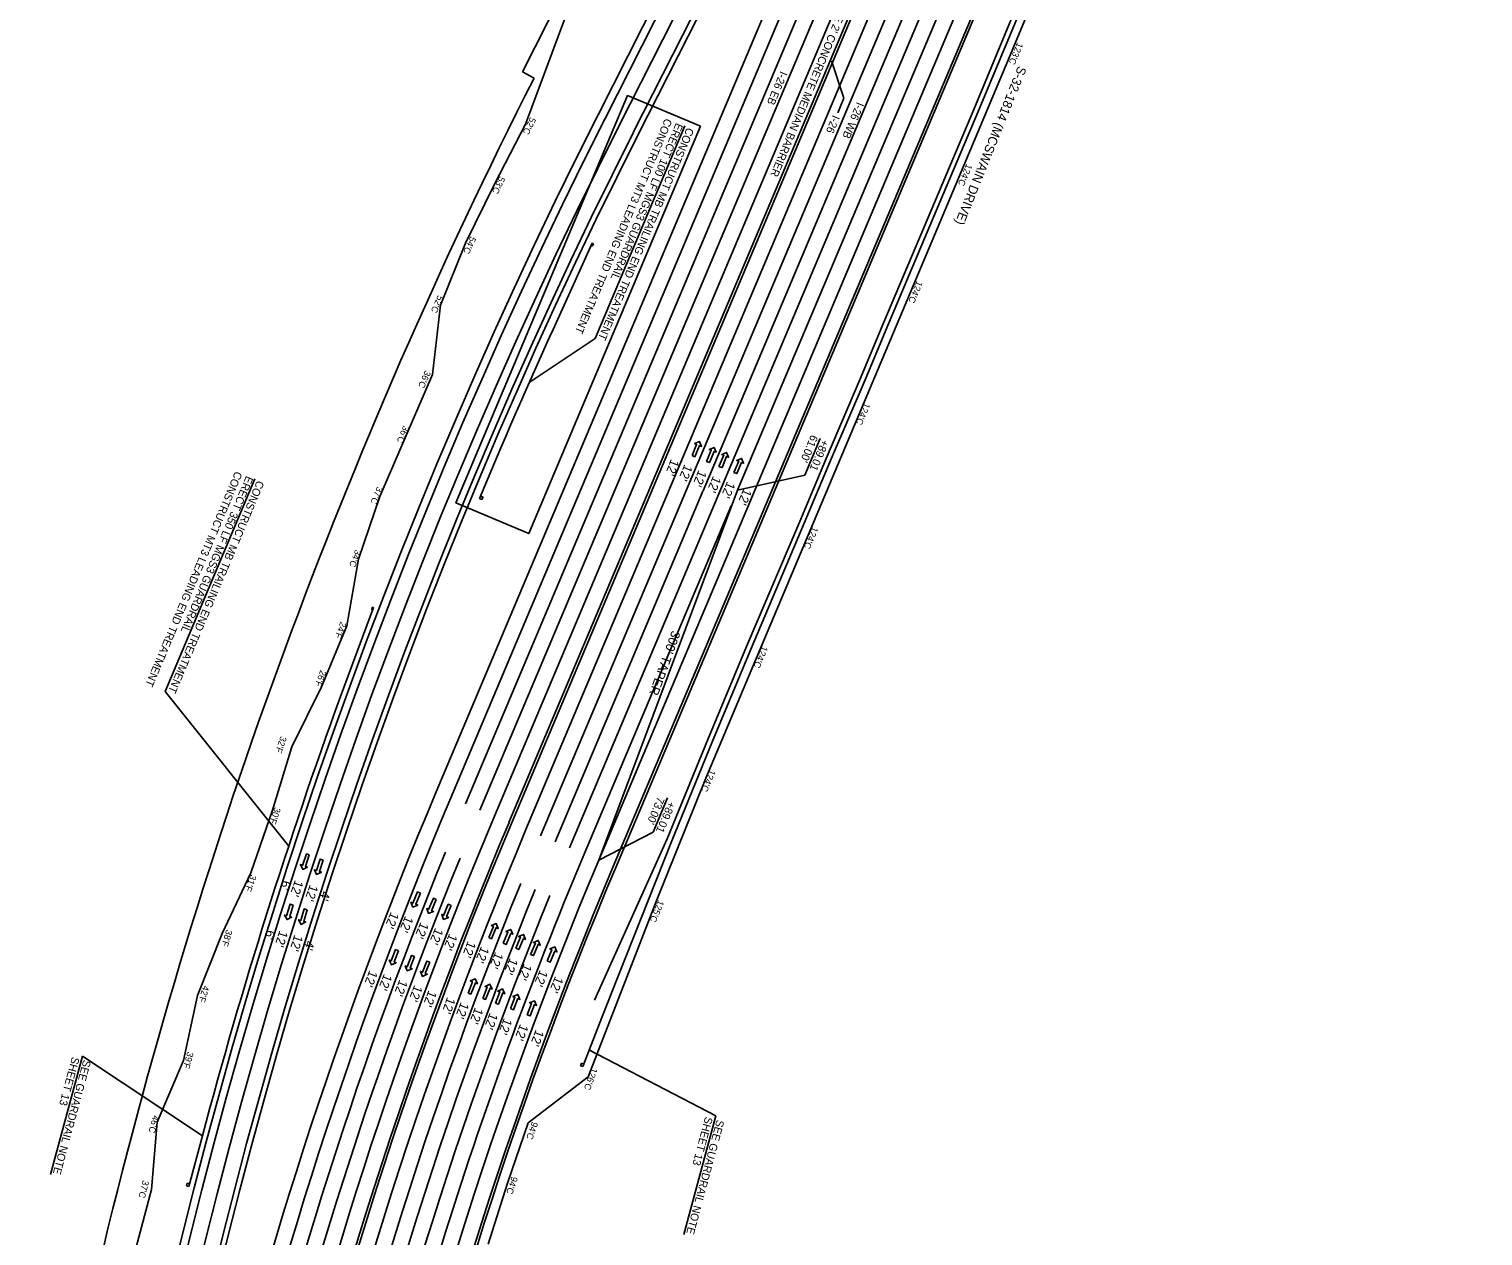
# Model space of a CAD drawing. Extents: x 1966090 to 1975830, y 788086 to 801233.
# Drawn here: x 1966292 to 1967397, y 791849 to 792766 of the extents above; entities that cross this region are included whole.
import ezdxf

# ---------------------------------------------------------------- set-up
doc = ezdxf.new("R2010")
doc.units = 0
for name, color, linetype in [('BR_PRESTRESSED BEAM', 7, 'Continuous'), ('BR_PROPOSED_DRAINAGE', 7, 'Continuous'), ('BR_REBAR', 7, 'Continuous'), ('RD_EX_Driveway_txCode', 7, 'Continuous'), ('RD_EX_RW_TX', 7, 'Continuous'), ('RD_EX_SU_Gas', 7, 'Continuous'), ('RD_EX_SU_H2O', 7, 'Continuous'), ('RD_EX_TX_Dam_ELEV', 7, 'Continuous'), ('RD_PD_PaveShd', 7, 'Continuous'), ('RD_Sketch6', 7, 'Continuous'), ('RD_Sketch8', 7, 'Continuous')]:
    doc.layers.add(name, color=color, linetype=linetype)

msp = doc.modelspace()

# ---------------------------------------------------------------- linework, layer by layer
at = {"layer": 'BR_PRESTRESSED BEAM'}
for p, q in [((1966690.3, 792537.7), (1966720.1, 792603.3)), ((1966719.3, 792601.4), (1966720.1, 792603.3)), ((1966720, 792601.1), (1966719.3, 792601.4)), ((1966721, 792602.9), (1966720, 792601.1)), ((1966720.1, 792603.3), (1966721, 792602.9)), ((1966649.9, 792446.2), (1966634.4, 792409.4)), ((1966635.2, 792411.2), (1966634.4, 792409.4)), ((1966634.4, 792409.4), (1966636.3, 792408.6)), ((1966637.1, 792410.4), (1966635.2, 792411.2)), ((1966636.3, 792408.6), (1966637.1, 792410.4)), ((1966528.8, 792258.9), (1966554, 792326.4)), ((1966553, 792326.7), (1966552.6, 792324.8)), ((1966552.6, 792324.8), (1966553.3, 792324.5)), ((1966554, 792326.4), (1966553, 792326.7)), ((1966553.3, 792324.5), (1966554, 792326.4)), ((1966727.5, 792014.9), (1966713, 791977.6)), ((1966711.2, 791978.3), (1966711.9, 791980.2)), ((1966713, 791977.6), (1966711.2, 791978.3)), ((1966711.9, 791980.2), (1966713.8, 791979.5)), ((1966713.8, 791979.5), (1966713, 791977.6)), ((1966423.9, 791925.1), (1966413.7, 791886.4)), ((1966411.8, 791886.9), (1966412.3, 791888.9)), ((1966413.7, 791886.4), (1966411.8, 791886.9)), ((1966412.3, 791888.9), (1966414.2, 791888.4)), ((1966414.2, 791888.4), (1966413.7, 791886.4))]:
    msp.add_line(p, q, dxfattribs=at)
msp.add_lwpolyline([(1966727.5, 792014.9), (1966739.3, 792045), (1966780.5, 792149.2), (1966780.6, 792149.3), (1966811.4, 792224.9), (1966840.8, 792295.4), (1966881.1, 792390.5), (1966902, 792440), (1966926.6, 792497.7), (1966945.1, 792542), (1966981.4, 792627.9), (1967013.4, 792703.6), (1967044.7, 792778.8), (1967071.9, 792844.4), (1967099.3, 792909.5), (1967127.2, 792975.7), (1967171.8, 793081), (1967207.1, 793164.5), (1967218.3, 793191.6)], dxfattribs=at)
for radius, start, end in [(3966, 155.4648, 156.9094), (4010, 160.0521, 165.053)]:
    msp.add_arc((1970298.2, 790890.8), radius, start, end, dxfattribs=at)
at = {"layer": 'BR_PROPOSED_DRAINAGE'}
for p, q in [((1967077.5, 792842.1), (1967039.1, 792749.8)), ((1966704.5, 792788.6), (1966669.5, 792693.8)), ((1967039.1, 792749.8), (1967000.5, 792657.6)), ((1966669.5, 792693.8), (1966646.2, 792648.8)), ((1966646.2, 792648.8), (1966623.8, 792603.3)), ((1967000.5, 792657.6), (1966806.4, 792196.7)), ((1966623.8, 792603.3), (1966604.8, 792556.3)), ((1966604.8, 792556.3), (1966598.6, 792503.7)), ((1966598.6, 792503.7), (1966578.8, 792457.3)), ((1966578.8, 792457.3), (1966558.8, 792411)), ((1966558.8, 792411), (1966542.5, 792363.2)), ((1966542.5, 792363.2), (1966533.7, 792312.7)), ((1966514.4, 792266.1), (1966533.7, 792312.7)), ((1966514.4, 792266.1), (1966491.8, 792220.7)), ((1966491.8, 792220.7), (1966477.2, 792172.5)), ((1966806.4, 792196.7), (1966769.2, 792104.4)), ((1966477.2, 792172.5), (1966460.6, 792124.9)), ((1966460.6, 792124.9), (1966438.9, 792078.8)), ((1966769.2, 792104.4), (1966717, 791969.9)), ((1966438.9, 792078.8), (1966420.2, 792031.7)), ((1966420.2, 792031.7), (1966409.6, 791982.2)), ((1966389.5, 791935.3), (1966409.6, 791982.2)), ((1966717, 791969.9), (1966671.4, 791934.9)), ((1966389.5, 791935.3), (1966385.1, 791884.3)), ((1966671.4, 791934.9), (1966655.8, 791888.9)), ((1966655.8, 791888.9), (1966640.9, 791842.7)), ((1966385.1, 791884.3), (1966372.2, 791835.5))]:
    msp.add_line(p, q, dxfattribs=at)
at = {"layer": 'BR_REBAR'}
for p, q in [((1967372.9, 793640.1), (1966736.1, 792129.8)), ((1967374.7, 793639.3), (1966737.9, 792129))]:
    msp.add_line(p, q, dxfattribs=at)
for radius, end in [(3190, 179.2174), (3188, 179.2164)]:
    msp.add_arc((1969675.5, 790890.4), radius, 157.1374, end, dxfattribs=at)
at = {"layer": 'RD_EX_Driveway_txCode'}
for points in [[(1966795.9, 792442.1), (1966798.1, 792441.1), (1966801.7, 792449.6), (1966803.2, 792448.9), (1966801.7, 792452.6), (1966797.9, 792451.1), (1966799.4, 792450.5)], [(1966806.9, 792437.6), (1966809.1, 792436.7), (1966812.7, 792445.1), (1966814.2, 792444.5), (1966812.7, 792448.2), (1966809, 792446.7), (1966810.5, 792446.1)], [(1966816.4, 792433.8), (1966818.7, 792432.9), (1966822.2, 792441.3), (1966823.7, 792440.7), (1966822.2, 792444.4), (1966818.5, 792442.9), (1966820, 792442.2)], [(1966827.8, 792429.2), (1966830, 792428.3), (1966833.6, 792436.7), (1966835.1, 792436.1), (1966833.6, 792439.8), (1966829.9, 792438.3), (1966831.4, 792437.7)], [(1966505.1, 792138.5), (1966502.9, 792139.2), (1966499.9, 792130.5), (1966498.4, 792131.1), (1966500.2, 792127.5), (1966503.7, 792129.2), (1966502.2, 792129.8)], [(1966515.7, 792134.6), (1966513.4, 792135.3), (1966510.5, 792126.7), (1966509, 792127.2), (1966510.7, 792123.6), (1966514.3, 792125.4), (1966512.8, 792125.9)], [(1966589.6, 792109.4), (1966587.4, 792110.3), (1966583.8, 792101.9), (1966582.3, 792102.5), (1966583.8, 792098.8), (1966587.5, 792100.3), (1966586, 792101)], [(1966492.9, 792100.4), (1966490.6, 792101.1), (1966487.9, 792092.3), (1966486.3, 792092.8), (1966488.2, 792089.3), (1966491.7, 792091.1), (1966490.2, 792091.6)], [(1966503.6, 792096.7), (1966501.3, 792097.5), (1966498.6, 792088.7), (1966497, 792089.2), (1966498.9, 792085.6), (1966502.4, 792087.5), (1966500.9, 792088)], [(1966601.6, 792104.6), (1966599.4, 792105.5), (1966595.8, 792097.1), (1966594.3, 792097.7), (1966595.8, 792094), (1966599.5, 792095.5), (1966598, 792096.1)], [(1966613, 792100), (1966610.7, 792101), (1966607.2, 792092.5), (1966605.7, 792093.2), (1966607.2, 792089.4), (1966610.9, 792090.9), (1966609.4, 792091.6)], [(1966641.4, 792075.7), (1966643.6, 792074.8), (1966647.2, 792083.2), (1966648.7, 792082.6), (1966647.2, 792086.3), (1966643.5, 792084.8), (1966645, 792084.2)], [(1966652.5, 792071.3), (1966654.7, 792070.4), (1966658.2, 792078.8), (1966659.7, 792078.2), (1966658.2, 792081.9), (1966654.5, 792080.4), (1966656, 792079.7)], [(1966662, 792067.5), (1966664.2, 792066.5), (1966667.8, 792075), (1966669.3, 792074.3), (1966667.8, 792078.1), (1966664.1, 792076.6), (1966665.6, 792075.9)], [(1966573, 792065.6), (1966570.7, 792066.5), (1966567.4, 792058), (1966565.9, 792058.6), (1966567.5, 792054.9), (1966571.1, 792056.5), (1966569.6, 792057.1)], [(1966673.3, 792062.9), (1966675.5, 792062), (1966679.1, 792070.4), (1966680.6, 792069.8), (1966679.1, 792073.5), (1966675.4, 792072), (1966676.9, 792071.4)], [(1966685.9, 792057.9), (1966688.1, 792056.9), (1966691.7, 792065.4), (1966693.2, 792064.8), (1966691.7, 792068.5), (1966688, 792067), (1966689.5, 792066.3)], [(1966585.1, 792061.2), (1966582.8, 792062.1), (1966579.5, 792053.5), (1966578, 792054.1), (1966579.6, 792050.4), (1966583.2, 792052), (1966581.7, 792052.6)], [(1966596.6, 792057), (1966594.3, 792057.8), (1966591, 792049.3), (1966589.5, 792049.9), (1966591.1, 792046.2), (1966594.7, 792047.8), (1966593.2, 792048.4)], [(1966625.7, 792033.5), (1966627.9, 792032.7), (1966631.3, 792041.2), (1966632.8, 792040.6), (1966631.2, 792044.3), (1966627.5, 792042.7), (1966629, 792042.1)], [(1966636.9, 792029.4), (1966639.1, 792028.6), (1966642.5, 792037.1), (1966644, 792036.5), (1966642.4, 792040.2), (1966638.7, 792038.6), (1966640.2, 792038)], [(1966646.5, 792025.9), (1966648.8, 792025), (1966652.1, 792033.6), (1966653.6, 792033), (1966652, 792036.6), (1966648.3, 792035), (1966649.9, 792034.4)], [(1966658, 792021.7), (1966660.2, 792020.8), (1966663.6, 792029.3), (1966665.1, 792028.7), (1966663.5, 792032.4), (1966659.8, 792030.8), (1966661.3, 792030.2)], [(1966670.7, 792017), (1966672.9, 792016.1), (1966676.3, 792024.7), (1966677.8, 792024.1), (1966676.2, 792027.7), (1966672.5, 792026.1), (1966674, 792025.5)]]:
    msp.add_lwpolyline(points, close=True, dxfattribs=at)
at = {"layer": 'RD_EX_SU_Gas'}
for p, q in [((1967295.5, 793770.5), (1966623.7, 792177.2)), ((1967306.5, 793765.8), (1966634.7, 792172.5)), ((1967352.6, 793746.4), (1966680.8, 792153.1)), ((1967374.7, 793737.1), (1966702.9, 792143.8)), ((1967363.7, 793741.7), (1966804.4, 792415.3)), ((1966740.5, 792692.8), (1966970.9, 793147.7)), ((1966804.2, 792414.9), (1966691.9, 792148.4)), ((1966714, 792139.1), (1966825.6, 792403.9))]:
    msp.add_line(p, q, dxfattribs=at)
for centre, radius, start, end in [((1970298.2, 790890.8), 3988, 153.1374, 186.3991), ((1969675.5, 790890.4), 3312, 157.822, 177.0114), ((1969675.5, 790890.4), 3300, 157.822, 177.0114), ((1969675.5, 790890.4), 3214, 157.1374, 162.7868), ((1969675.5, 790890.4), 3250, 157.8325, 179.1982), ((1969675.5, 790890.4), 3238, 157.8325, 179.1982), ((1969675.5, 790890.4), 3226, 157.8325, 179.1982)]:
    msp.add_arc(centre, radius, start, end, dxfattribs=at)
at = {"layer": 'RD_EX_TX_Dam_ELEV'}
for p, q in [((1966919.3, 793231.7), (1966667, 792733.5)), ((1966667, 792733.5), (1966675.9, 792728.9)), ((1966721.7, 792028.1), (1966777.1, 792150.7))]:
    msp.add_line(p, q, dxfattribs=at)
msp.add_lwpolyline([(1966777.1, 792150.7), (1966808, 792226.3), (1966837.4, 792296.9), (1966877.7, 792392), (1966898.6, 792441.5), (1966923.1, 792499.1), (1966941.6, 792543.4), (1966978, 792629.4), (1967010, 792705), (1967041.2, 792780.2), (1967068.5, 792845.9), (1967095.9, 792910.9), (1967123.7, 792977.2), (1967168.4, 793082.5), (1967203.6, 793165.9), (1967286.6, 793366.3)], dxfattribs=at)
msp.add_arc((1970298.2, 790890.8), 4062, 153.0951, 166.4711, dxfattribs=at)
at = {"layer": 'RD_PD_PaveShd'}
for p, q in [((1967328.6, 793756.5), (1966656.8, 792163.2)), ((1967330.5, 793755.7), (1966658.7, 792162.4)), ((1967372.9, 793640.1), (1966736.1, 792129.8)), ((1966724.5, 792701), (1966976.8, 793199.2)), ((1966754.8, 792685.6), (1966991.1, 793152.1)), ((1966933.9, 792974.6), (1966601.6, 792186.5))]:
    msp.add_line(p, q, dxfattribs=at)
for centre, radius, start, end in [((1970298.2, 790890.8), 4006, 153.1374, 186.3991), ((1970298.2, 790890.8), 3972, 153.1374, 186.1282), ((1969675.5, 790890.4), 3336, 157.1374, 177.0114), ((1969675.5, 790890.4), 3276, 157.1374, 179.1982), ((1969675.5, 790890.4), 3274, 157.1374, 179.1982), ((1969675.5, 790890.4), 3190, 157.1374, 179.2174)]:
    msp.add_arc(centre, radius, start, end, dxfattribs=at)
at = {"layer": 'RD_Sketch6'}
for p, q in [((1966911.3, 792713.5), (1966902, 792742.1)), ((1966906.7, 792702.5), (1966911.3, 792713.5)), ((1966790.4, 792692.5), (1966722.2, 792530.9)), ((1966722.2, 792530.9), (1966672.9, 792497.9)), ((1966881.6, 792427.2), (1966893.2, 792454.9)), ((1966463.8, 792424.3), (1966395.6, 792262.7)), ((1966395.6, 792262.7), (1966489.5, 792145.2)), ((1966766.3, 792155.8), (1966777.3, 792181.8)), ((1966717.6, 791990.3), (1966813.9, 791940.1)), ((1966308.5, 791895.5), (1966332.8, 791985.6)), ((1966423.9, 791925.1), (1966332.8, 791985.6)), ((1966789.7, 791850), (1966813.9, 791940.1))]:
    msp.add_line(p, q, dxfattribs=at)
msp.add_lwpolyline([(1966802.4, 792692.3), (1966671.8, 792382.7), (1966616.5, 792406.1), (1966747, 792715.6)], close=True, dxfattribs=at)
for points in [[(1966881.6, 792427.2), (1966830.5, 792415.6)], [(1966766.3, 792155.8), (1966725, 792134.5)]]:
    msp.add_lwpolyline(points, dxfattribs=at)
at = {"layer": 'RD_Sketch8'}
for p, q in [((1967317.6, 793761.2), (1966645.8, 792167.9)), ((1967341.5, 793751.1), (1966669.7, 792157.8)), ((1967385.8, 793732.4), (1966830.5, 792415.6)), ((1967396.8, 793727.8), (1966725, 792134.5)), ((1966729.8, 792698.2), (1966982.2, 793196.5)), ((1966751.2, 792687.4), (1967003.6, 793185.6)), ((1966933.3, 792942.5), (1966612.6, 792181.9)), ((1966830.5, 792415.6), (1966725, 792134.5))]:
    msp.add_line(p, q, dxfattribs=at)
for centre, radius, start, end in [((1970298.2, 790890.8), 4000, 153.1374, 186.3991), ((1970298.2, 790890.8), 3976, 153.1374, 186.1303), ((1969675.5, 790890.4), 3324, 157.1374, 177.0114), ((1969675.5, 790890.4), 3288, 157.1374, 177.0114), ((1969675.5, 790890.4), 3262, 157.1374, 179.1982), ((1969675.5, 790890.4), 3202, 157.1374, 179.1982)]:
    msp.add_arc(centre, radius, start, end, dxfattribs=at)

# ---------------------------------------------------------------- texts
at = {"layer": 'RD_EX_Driveway_txCode'}
for s, height, rotation, p in [("REMOVE AND REPLACE 2' CONCRETE MEDIAN BARRIER", 6, 247.4535, (1966939.8, 792858.9)), ("12'", 7, 248.9372, (1966780, 792439.7)), ("12'", 7, 246.981, (1966790.3, 792435.7)), ("12'", 7, 246.981, (1966801, 792431.4)), ("12'", 7, 246.981, (1966812, 792426.9)), ("12'", 7, 246.981, (1966822.7, 792422.7)), ("12'", 7, 246.981, (1966835.2, 792417.4)), ("300' TAPER", 7, 250.0706, (1966780.7, 792309.4)), ("6'", 7, 257.2178, (1966484.4, 792119.5)), ("12'", 7, 250.689, (1966494.3, 792119.8)), ("12'", 7, 250.689, (1966505.6, 792116.3)), ("4'", 7, 255.0854, (1966514.4, 792111.4)), ("12'", 7, 246.981, (1966567.2, 792095.6)), ("12'", 7, 246.981, (1966578.1, 792092.6)), ("12'", 7, 246.981, (1966589.8, 792087.9)), ("6'", 7, 257.2178, (1966472.5, 792081.8)), ("12'", 7, 252.1463, (1966482.5, 792081.4)), ("12'", 7, 252.1463, (1966493.9, 792078.2)), ("12'", 7, 246.981, (1966600.9, 792083.4)), ("12'", 7, 246.981, (1966611.6, 792079.1)), ("4'", 7, 255.0854, (1966502.5, 792073.8)), ("12'", 7, 248.9372, (1966625.6, 792073.4)), ("12'", 7, 246.981, (1966635.8, 792069.4)), ("12'", 7, 246.981, (1966646.5, 792065.1)), ("12'", 7, 246.981, (1966657.6, 792060.6)), ("12'", 7, 246.981, (1966668.2, 792056.3)), ("12'", 7, 248.6813, (1966550.9, 792051.2)), ("12'", 7, 248.6813, (1966561.9, 792048.5)), ("12'", 7, 248.6813, (1966573.7, 792044.1)), ("12'", 7, 246.981, (1966680.4, 792051.5)), ("12'", 7, 246.981, (1966692.1, 792046.7)), ("12'", 7, 248.6813, (1966585, 792040)), ("12'", 7, 248.6813, (1966595.8, 792036)), ("12'", 7, 250.6375, (1966609.9, 792030.7)), ("12'", 7, 248.6813, (1966620.3, 792027)), ("12'", 7, 248.6813, (1966631.1, 792023)), ("12'", 7, 248.6813, (1966642.3, 792018.9)), ("12'", 7, 248.6813, (1966653.1, 792014.9)), ("12'", 7, 248.6813, (1966665.4, 792010.4)), ("12'", 7, 248.6813, (1966677.3, 792006.1))]:
    msp.add_text(s, height=height, rotation=rotation, dxfattribs=at).set_placement(p)
at = {"layer": 'RD_EX_RW_TX'}
for s, rotation, p in [("123'C", 247.1374, (1967043.1, 792756.3)), ("52'C", 243.5795, (1966673.1, 792699.6)), ("124'C", 247.1374, (1967004.5, 792664.1)), ("53'C", 244.2957, (1966649.6, 792654.6)), ("54'C", 245.0119, (1966627.6, 792609)), ("124'C", 247.1374, (1966966.8, 792575.1)), ("52'C", 245.7281, (1966602.9, 792564.2)), ("36'C", 246.4443, (1966593.1, 792507.1)), ("124'C", 247.1374, (1966926.9, 792482.5)), ("36'C", 247.1605, (1966576.7, 792465.2)), ("37'C", 247.8767, (1966556.6, 792418.8)), ("124'C", 247.1374, (1966887.4, 792388.3)), ("34'C", 248.5929, (1966540.2, 792371)), ("24'F", 249.3091, (1966528.9, 792316.1)), ("124'C", 247.1374, (1966849.2, 792297.7)), ("26'F", 250.0253, (1966513.6, 792279.3)), ("32'F", 250.7415, (1966483.4, 792229.1)), ("124'C", 247.1374, (1966809.4, 792203.7)), ("30'F", 251.4577, (1966478.8, 792175.1)), ("31'F", 249.3144, (1966460.5, 792123.8)), ("125'C", 247.3296, (1966770.3, 792104.5)), ("38'F", 252.8901, (1966442.1, 792082)), ("42'F", 253.6063, (1966424.5, 792039.6)), ("39'F", 254.3225, (1966412.5, 791989.2)), ("126'C", 249.9538, (1966719.6, 791977.1)), ("46'C", 255.0387, (1966386.4, 791941)), ("94'C", 250.8286, (1966674.3, 791936.1)), ("37'C", 255.7549, (1966378.6, 791891.5)), ("94'C", 251.7033, (1966658.9, 791894.5))]:
    msp.add_text(s, height=5, rotation=rotation, dxfattribs=at).set_placement(p)
at = {"layer": 'RD_EX_SU_H2O'}
for s, height, rotation, p in [('S-32-1814 (MCSWAIN DRIVE)', 7, 248.0553, (1967043.8, 792738.6)), ('I-26 EB', 6, 247.071, (1966863.1, 792734.6)), ('I-26 WB', 6, 247.071, (1966921.3, 792711.1))]:
    msp.add_text(s, height=height, rotation=rotation, dxfattribs=at).set_placement(p)
at = {"layer": 'RD_Sketch6'}
for s, rotation, p in [('CONSTRUCT MT3 LEADING END TREATMENT', 247.1374, (1966775.5, 792698.7)), ('ERECT 100 LF MGS3 GUARDRAIL', 247.1374, (1966783.8, 792695.2)), ('I-26', 247.246, (1966902.9, 792701.2)), ('CONSTRUCT MB TRAILING END TREATMENT', 247.1374, (1966792.1, 792691.7)), ("61.00'", 247.1375, (1966886.4, 792458.2)), ('+89.01', 247.1375, (1966894.7, 792454.7)), ('CONSTRUCT MT3 LEADING END TREATMENT', 247.1374, (1966448.9, 792430.5)), ('CONSTRUCT MB TRAILING END TREATMENT', 247.1374, (1966465.5, 792423.5)), ('ERECT 350 LF MGS3 GUARDRAIL', 247.1374, (1966457.2, 792427)), ("73.00'", 247.1375, (1966769.8, 792183.1)), ('+89.01', 247.1375, (1966778, 792179.6)), ('SEE GUARDRAIL NOTE', 254.9752, (1966333.5, 791983.1)), ('SHEET 13', 254.9752, (1966324.8, 791985.4)), ('SEE GUARDRAIL NOTE', 254.9752, (1966814.7, 791937.6)), ('SHEET 13', 254.9752, (1966806, 791939.9))]:
    msp.add_text(s, height=6, rotation=rotation, dxfattribs=at).set_placement(p)

doc.saveas('drawing.dxf')
